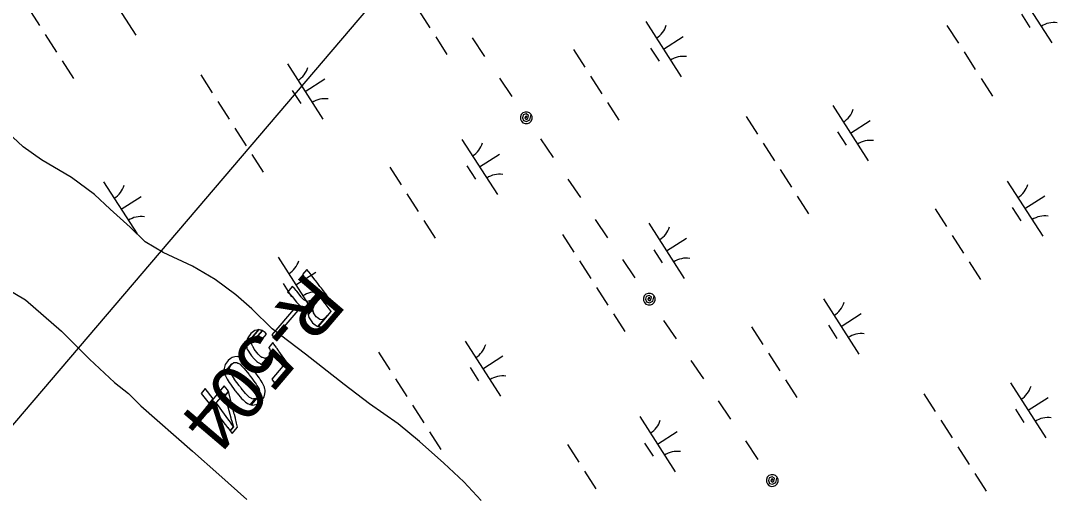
# Model space of a CAD drawing. Extents: x 3962991 to 3983549, y 181631 to 204078.
# Drawn here: x 3970895 to 3971685, y 196865 to 197226 of the extents above; entities that cross this region are included whole.
import ezdxf

# ---------------------------------------------------------------- set-up
doc = ezdxf.new("R2010")
doc.units = 0
for name, color, linetype in [('V-ANNO-MASK', 7, 'Continuous'), ('V-ANNO-MASK2', 7, 'Continuous'), ('V-RIVR-EDGE', 7, 'Continuous'), ('V-RIVR-RANG-IDEN', 7, 'Continuous'), ('V-UTIL-LINE', 7, 'Continuous'), ('V-WETL-SWMP', 7, 'Continuous')]:
    doc.layers.add(name, color=color, linetype=linetype)

msp = doc.modelspace()

# ---------------------------------------------------------------- linework, layer by layer
at = {"layer": 'V-ANNO-MASK2'}
for points in [[(3971114.6, 197035.12), (3971113.38, 197036.71), (3971110.05, 197032.8), (3971111.27, 197031.21), (3971111.53, 197030.87), (3971112.78, 197029.26), (3971113.16, 197028.76), (3971116.45, 197024.49), (3971116.87, 197023.95), (3971118.41, 197021.95), (3971119.05, 197021.13), (3971120.06, 197019.82), (3971120.78, 197018.87), (3971121.01, 197018.57), (3971121.21, 197018.32), (3971112.09, 197007.59), (3971113.72, 197007.73), (3971116.3, 197009.24), (3971115.18, 197007.38), (3971114.16, 197004.26), (3971114.22, 197003.89), (3971123.72, 197015.06), (3971123.84, 197014.91), (3971124.49, 197014.06), (3971125.57, 197012.67), (3971125.91, 197012.22), (3971128.06, 197009.43), (3971128.63, 197008.7), (3971130.23, 197006.62), (3971131.4, 197005.11), (3971131.64, 197004.79), (3971131.65, 197004.79), (3971131.75, 197004.66), (3971131.79, 197004.6), (3971121.99, 196993.07), (3971125.62, 196992.94), (3971128.9, 196994.87), (3971131.91, 196998.14), (3971137.79, 197005.04), (3971137.68, 197005.19), (3971136.9, 197006.2), (3971135.12, 197008.51), (3971135.08, 197008.57), (3971134.97, 197008.7), (3971134.73, 197009.02), (3971133.56, 197010.54), (3971131.96, 197012.61), (3971131.39, 197013.35), (3971129.24, 197016.13), (3971128.9, 197016.58), (3971127.82, 197017.98), (3971127.17, 197018.83), (3971127.05, 197018.98), (3971126.87, 197019.21), (3971126.1, 197020.22), (3971125.88, 197020.51), (3971125.26, 197021.3), (3971124.54, 197022.24), (3971124.35, 197022.49), (3971124.12, 197022.79), (3971123.39, 197023.73), (3971122.37, 197025.04), (3971121.74, 197025.87), (3971120.2, 197027.87), (3971119.79, 197028.41), (3971116.49, 197032.68), (3971116.11, 197033.17), (3971114.86, 197034.79)], [(3971103.72, 197022.33), (3971102.32, 197023.71), (3971098.69, 197019.44), (3971100.22, 197018.21), (3971100.51, 197017.92), (3971101.92, 197016.48), (3971102.3, 197016), (3971105.66, 197011.8), (3971106.09, 197011.27), (3971107.83, 197009.52), (3971108.55, 197008.79), (3971110.05, 197008.05), (3971111.13, 197007.51), (3971111.65, 197007.56), (3971112.09, 197007.59), (3971118.06, 197014.62), (3971116.09, 197012.78), (3971115.51, 197012.66), (3971113.63, 197012.25), (3971112.11, 197012.98), (3971111.16, 197013.43), (3971109.47, 197015.24), (3971109.01, 197015.73), (3971105.71, 197020.01), (3971105.32, 197020.48), (3971104.01, 197022.03)], [(3971106.75, 197005.45), (3971104.79, 197008), (3971086.77, 196986.81), (3971088.73, 196984.26)], [(3971118.92, 197009.12), (3971120.99, 197011.85), (3971114.22, 197003.89), (3971114.26, 197003.65), (3971114.5, 197002.31), (3971117.94, 197006.36)], [(3971118.39, 197004.23), (3971117.94, 197006.36), (3971114.5, 197002.31), (3971114.88, 197000.1), (3971115.21, 196999.63), (3971117.27, 196996.74), (3971117.81, 196995.98), (3971119.87, 196994.44), (3971121.38, 196993.32), (3971121.69, 196993.08), (3971121.9, 196993.08), (3971127.39, 196999.53), (3971126.84, 196999.15), (3971125.55, 196998.23), (3971123.23, 196998.39), (3971121.26, 197000.03), (3971120.56, 197000.61), (3971118.54, 197003.55)], [(3971129.1, 197001.43), (3971127.38, 196999.53), (3971121.9, 196993.08), (3971121.99, 196993.07)], [(3971071.83, 196988.48), (3971070.87, 196987.71), (3971068.47, 196984.52), (3971068.01, 196983.23), (3971067.12, 196980.68), (3971067.29, 196979.47), (3971076.91, 196990.78), (3971075.39, 196990.41), (3971073.79, 196990.03)], [(3971078.18, 196990.41), (3971076.9, 196990.77), (3971067.29, 196979.47), (3971067.51, 196977.86), (3971073.07, 196984.4), (3971074.75, 196985.66), (3971075.07, 196985.9), (3971076.05, 196985.9), (3971076.05, 196985.91), (3971076.17, 196985.91), (3971079.64, 196989.99), (3971079.54, 196990.01), (3971078.76, 196990.24), (3971078.67, 196990.27)], [(3971080.09, 196989.65), (3971079.63, 196989.98), (3971076.17, 196985.91), (3971076.91, 196985.91), (3971077.08, 196985.82), (3971078.48, 196984.99), (3971078.54, 196984.94), (3971079.67, 196983.84), (3971082.68, 196987.38), (3971081.61, 196988.55), (3971081.56, 196988.6), (3971080.25, 196989.54)], [(3971071.69, 196982.06), (3971073.07, 196984.4), (3971067.51, 196977.87), (3971067.59, 196977.24), (3971067.61, 196977.13), (3971067.74, 196976.14), (3971067.8, 196976.06), (3971068.11, 196975.56), (3971068.22, 196975.4), (3971069.12, 196973.98), (3971069.17, 196973.91), (3971070.21, 196972.27), (3971071.16, 196970.78), (3971073.28, 196968.48), (3971075.23, 196966.37), (3971075.37, 196966.22), (3971075.91, 196965.93), (3971076.35, 196965.69), (3971077.79, 196964.89), (3971078.09, 196964.72), (3971078.84, 196964.3), (3971078.84, 196964.31), (3971079.01, 196964.21), (3971083.64, 196969.65), (3971083.25, 196969.49), (3971081.55, 196968.79), (3971081.2, 196968.91), (3971079.55, 196969.45), (3971079.04, 196969.61), (3971078.6, 196970.02), (3971078.45, 196970.15), (3971076.34, 196972.08), (3971074.41, 196974.6), (3971073.35, 196975.96), (3971072.43, 196977.75), (3971072.39, 196977.82), (3971071.6, 196979.37), (3971071.61, 196979.67), (3971071.64, 196980.59), (3971071.65, 196980.73), (3971071.69, 196981.92)], [(3971087.68, 196980.69), (3971087.55, 196980.86), (3971084.42, 196977.18), (3971084.54, 196977), (3971084.86, 196976.45), (3971085.13, 196976), (3971085.55, 196974.02), (3971085.42, 196973.34), (3971085.43, 196973.35), (3971085.09, 196971.66), (3971083.63, 196969.65), (3971079.01, 196964.21), (3971079.31, 196964.04), (3971080.44, 196964.11), (3971087.88, 196972.85), (3971088.68, 196971.74), (3971088.99, 196971.31), (3971089.23, 196970.98), (3971095.06, 196962.87), (3971086.66, 196952.99), (3971089.15, 196949.77), (3971100.39, 196962.99), (3971098, 196966.33), (3971092.17, 196974.44), (3971091.93, 196974.76), (3971091.62, 196975.2), (3971090.82, 196976.31), (3971090.33, 196977), (3971090.13, 196977.28), (3971090.01, 196977.44), (3971089.51, 196978.15), (3971089.3, 196978.43), (3971088.33, 196979.77), (3971088.04, 196980.19)], [(3971087.85, 196970.76), (3971087.88, 196972.85), (3971080.44, 196964.11), (3971082.29, 196964.22), (3971083, 196964.26), (3971084.35, 196965.24), (3971085.6, 196966.16), (3971085.6, 196966.16), (3971087.26, 196968.67), (3971087.52, 196969.58)], [(3971054.94, 196968.38), (3971053.53, 196967.27), (3971051.28, 196964.08), (3971051.04, 196963.17), (3971050.24, 196960.22), (3971050.52, 196958.82), (3971050.68, 196957.98), (3971056.32, 196964.61), (3971056.57, 196964.77), (3971057.92, 196965.62), (3971058.53, 196965.65), (3971059.03, 196965.68), (3971060, 196965.73), (3971060.98, 196965.19), (3971060.99, 196965.19), (3971062.56, 196964.32), (3971063.49, 196963.37), (3971064.45, 196962.39), (3971065.47, 196961.35), (3971065.57, 196961.24), (3971069.12, 196956.79), (3971069.55, 196956.27), (3971070.35, 196955.25), (3971070.72, 196954.75), (3971070.72, 196954.76), (3971073.87, 196950.44), (3971073.88, 196950.45), (3971074.13, 196950.1), (3971074.87, 196949.09), (3971075.44, 196948.08), (3971076.27, 196946.62), (3971076.99, 196945.33), (3971077.02, 196945.21), (3971077.3, 196943.84), (3971077.42, 196943.24), (3971077.55, 196942.63), (3971077.27, 196941.61), (3971077.28, 196941.61), (3971077, 196940.59), (3971075.77, 196938.99), (3971071.07, 196933.47), (3971071.85, 196933.2), (3971073.29, 196933.49), (3971075.48, 196933.93), (3971076.95, 196935.07), (3971080.85, 196939.66), (3971081.05, 196940.48), (3971081.78, 196943.47), (3971081.56, 196944.61), (3971081.37, 196945.58), (3971081.34, 196945.7), (3971081.24, 196946.27), (3971081.12, 196946.84), (3971081, 196947.45), (3971080.76, 196947.91), (3971080.2, 196948.96), (3971080.15, 196949.06), (3971079.45, 196950.37), (3971078.66, 196951.86), (3971078, 196952.77), (3971077.26, 196953.79), (3971077.01, 196954.14), (3971073.88, 196958.47), (3971073.5, 196958.95), (3971072.68, 196959.96), (3971072.25, 196960.48), (3971068.67, 196964.89), (3971068.57, 196965), (3971067.51, 196965.98), (3971066.5, 196966.91), (3971065.52, 196967.8), (3971064.22, 196968.99), (3971064.21, 196968.99), (3971063.1, 196969.38), (3971062.39, 196969.63), (3971062.02, 196969.76), (3971061.57, 196969.91), (3971061.09, 196970.09), (3971061, 196970.11), (3971060.33, 196970.35), (3971058.58, 196970.03), (3971056.54, 196969.64)], [(3971055.09, 196963.02), (3971056.32, 196964.61), (3971050.68, 196957.98), (3971050.71, 196957.87)], [(3971054.8, 196961.95), (3971055.08, 196963.02), (3971050.71, 196957.87), (3971050.82, 196957.27), (3971050.93, 196956.72), (3971051.02, 196956.26), (3971051.38, 196955.6), (3971051.94, 196954.56), (3971051.95, 196954.55), (3971052.84, 196952.89), (3971053.52, 196951.64), (3971054.34, 196950.49), (3971055.2, 196949.27), (3971055.2, 196949.28), (3971055.29, 196949.15), (3971058.62, 196944.45), (3971059.05, 196943.93), (3971059.88, 196942.93), (3971060.27, 196942.46), (3971063.62, 196938.39), (3971063.89, 196938.07), (3971064.81, 196937.27), (3971065.64, 196936.55), (3971066.82, 196935.51), (3971067.87, 196934.61), (3971067.94, 196934.54), (3971069.07, 196934.15), (3971069.07, 196934.16), (3971069.55, 196933.99), (3971070.05, 196933.82), (3971070.51, 196933.66), (3971074.19, 196937.98), (3971073.56, 196937.95), (3971072.89, 196937.91), (3971072.23, 196937.87), (3971071.22, 196938.39), (3971071.13, 196938.44), (3971069.86, 196939.08), (3971068.72, 196940.17), (3971067.93, 196940.93), (3971067.05, 196941.78), (3971066.74, 196942.06), (3971063.41, 196946.16), (3971063.02, 196946.64), (3971062.21, 196947.64), (3971061.81, 196948.19), (3971058.44, 196952.85), (3971058.34, 196952.97), (3971057.47, 196954.18), (3971056.74, 196955.44), (3971056.04, 196956.65), (3971055.1, 196958.27), (3971055.09, 196958.27), (3971054.82, 196959.64), (3971054.64, 196960.52), (3971054.55, 196960.97)], [(3971042.12, 196937.97), (3971036.08, 196945.82), (3971032.99, 196942.19), (3971039.03, 196934.34)], [(3971052.89, 196944.91), (3971050.57, 196947.91), (3971035.93, 196930.69), (3971038.25, 196927.7), (3971050.45, 196942.04), (3971050.92, 196940.32), (3971053.81, 196943.72)], [(3971058.13, 196926.53), (3971053.81, 196943.72), (3971050.92, 196940.32), (3971055.48, 196923.42), (3971055.6, 196922.98), (3971056.43, 196920.17), (3971056.48, 196920.03), (3971057.57, 196916.68), (3971055, 196913.65), (3971056.62, 196911.54), (3971060.69, 196916.32), (3971059.91, 196919.43), (3971059.01, 196923.01), (3971058.98, 196923.16), (3971058.24, 196926.08)], [(3971045.32, 196933.74), (3971044.43, 196934.96), (3971041.35, 196931.35), (3971042.28, 196930.16), (3971051.28, 196918.48), (3971051.52, 196918.17), (3971053.05, 196916.19), (3971053.12, 196916.09), (3971055, 196913.65), (3971057.57, 196916.68), (3971055.85, 196919.3), (3971055.78, 196919.41), (3971054.33, 196921.48), (3971054.1, 196921.79)], [(3971075.48, 196938.81), (3971074.18, 196937.98), (3971070.51, 196933.66), (3971070.97, 196933.5), (3971071.07, 196933.47), (3971075.77, 196938.99)], [(3971078.52, 196936.3), (3971080.85, 196939.66), (3971076.95, 196935.07), (3971078.51, 196936.29)]]:
    msp.add_lwpolyline(points, close=True, dxfattribs=at)
at = {"layer": 'V-RIVR-EDGE'}
msp.add_lwpolyline([(3970873.05, 197028.8), (3970899.17, 197013.36), (3970926.48, 196989.62), (3970947.85, 196968.25), (3970966.84, 196950.44), (3970977.53, 196942.13), (3970987.02, 196932.63), (3971026.2, 196898.2), (3971046.38, 196880.39), (3971067.75, 196861.4)], dxfattribs=at)
at = {"layer": 'V-UTIL-LINE'}
msp.add_line((3970065.58, 195951.74), (3971473.5, 197603.23), dxfattribs=at)
for points in [[(3971239.36, 197213.04), (3971248.9, 197198.97)], [(3971260.12, 197182.42), (3971269.66, 197168.35)], [(3971280.61, 197152.19), (3971281.13, 197153.53), (3971280, 197153.25), (3971279.53, 197151.96), (3971280.48, 197150.85), (3971281.93, 197151.73), (3971282.43, 197154.03), (3971280.61, 197155.13), (3971278.3, 197154.35), (3971277.76, 197152.13), (3971278.58, 197150.05), (3971280.9, 197149.37), (3971283.26, 197150.78), (3971284.33, 197154.72), (3971283.08, 197155.95), (3971281.45, 197156.61), (3971279.7, 197156.6), (3971278.08, 197155.92), (3971276.85, 197154.67), (3971276.19, 197153.04), (3971276.2, 197151.28), (3971276.88, 197149.67), (3971278.13, 197148.43), (3971279.76, 197147.77), (3971281.51, 197147.78), (3971283.13, 197148.47), (3971284.36, 197149.72), (3971285.02, 197151.34), (3971285.01, 197153.1), (3971284.33, 197154.72)], [(3971291.55, 197136.07), (3971301.08, 197121.99)], [(3971312.31, 197105.44), (3971321.85, 197091.37)], [(3971333.07, 197074.82), (3971342.61, 197060.74)], [(3971353.83, 197044.19), (3971363.37, 197030.12)], [(3971374.32, 197013.96), (3971374.84, 197015.3), (3971373.71, 197015.03), (3971373.24, 197013.74), (3971374.2, 197012.62), (3971375.65, 197013.51), (3971376.14, 197015.8), (3971374.32, 197016.9), (3971372.02, 197016.12), (3971371.47, 197013.9), (3971372.3, 197011.82), (3971374.61, 197011.15), (3971376.98, 197012.55), (3971378.04, 197016.49), (3971376.79, 197017.72), (3971375.17, 197018.38), (3971373.41, 197018.37), (3971371.79, 197017.69), (3971370.56, 197016.44), (3971369.9, 197014.81), (3971369.91, 197013.06), (3971370.59, 197011.44), (3971371.84, 197010.21), (3971373.47, 197009.54), (3971375.23, 197009.56), (3971376.84, 197010.24), (3971378.08, 197011.49), (3971378.74, 197013.12), (3971378.73, 197014.87), (3971378.04, 197016.49)], [(3971385.26, 196997.84), (3971394.8, 196983.77)], [(3971406.02, 196967.21), (3971415.56, 196953.14)], [(3971426.78, 196936.59), (3971436.32, 196922.52)], [(3971447.54, 196905.96), (3971457.08, 196891.89)], [(3971468.03, 196875.74), (3971468.55, 196877.08), (3971467.42, 196876.8), (3971466.96, 196875.51), (3971467.91, 196874.39), (3971469.36, 196875.28), (3971469.86, 196877.57), (3971468.03, 196878.68), (3971465.73, 196877.9), (3971465.19, 196875.67), (3971466.01, 196873.59), (3971468.32, 196872.92), (3971470.69, 196874.33), (3971471.76, 196878.26), (3971470.51, 196879.49), (3971468.88, 196880.16), (3971467.12, 196880.14), (3971465.51, 196879.46), (3971464.27, 196878.21), (3971463.61, 196876.58), (3971463.62, 196874.83), (3971464.31, 196873.21), (3971465.56, 196871.98), (3971467.18, 196871.32), (3971468.94, 196871.33), (3971470.56, 196872.01), (3971471.79, 196873.26), (3971472.45, 196874.89), (3971472.44, 196876.64), (3971471.76, 196878.26)]]:
    msp.add_lwpolyline(points, dxfattribs=at)
at = {"layer": 'V-WETL-SWMP'}
for p, q in [((3970956.13, 197257.26), (3970983.11, 197215.16)), ((3971654.11, 197251.36), (3971681.1, 197209.27)), ((3970901.22, 197235.96), (3970909.86, 197222.49)), ((3971198.63, 197234.19), (3971207.27, 197220.72)), ((3971371.63, 197225.54), (3971398.62, 197183.44)), ((3971657.87, 197231.2), (3971664.35, 197221.1)), ((3971601.18, 197222.68), (3971609.82, 197209.21)), ((3970914.17, 197215.75), (3970922.81, 197202.28)), ((3971211.59, 197213.99), (3971220.22, 197200.52)), ((3971385.12, 197204.49), (3971400.28, 197214.2)), ((3971316.73, 197204.24), (3971325.36, 197190.77)), ((3971375.39, 197205.38), (3971381.87, 197195.27)), ((3971614.14, 197202.47), (3971622.77, 197189.01)), ((3970927.13, 197195.55), (3970935.76, 197182.08)), ((3971098.58, 197193.3), (3971125.56, 197151.21)), ((3971032.7, 197184.83), (3971041.33, 197171.36)), ((3971112.07, 197172.26), (3971127.22, 197181.97)), ((3971329.68, 197184.03), (3971338.31, 197170.56)), ((3971627.09, 197182.27), (3971635.73, 197168.8)), ((3971102.33, 197173.14), (3971108.81, 197163.04)), ((3970897.39, 197130.08), (3970859.96, 197164.87)), ((3971045.65, 197164.63), (3971054.28, 197151.16)), ((3971342.63, 197163.83), (3971351.27, 197150.36)), ((3971514.08, 197161.58), (3971541.07, 197119.49)), ((3971448.2, 197153.11), (3971456.84, 197139.64)), ((3971527.57, 197140.54), (3971542.73, 197150.25)), ((3971058.6, 197144.42), (3971067.24, 197130.95)), ((3971517.84, 197141.43), (3971524.32, 197131.32)), ((3971231.6, 197135.76), (3971258.59, 197093.67)), ((3971461.15, 197132.91), (3971469.79, 197119.44)), ((3970911.24, 197120.09), (3970897.39, 197130.08)), ((3971071.55, 197124.22), (3971080.19, 197110.75)), ((3971245.09, 197114.72), (3971260.25, 197124.43)), ((3970934.09, 197106.62), (3970911.24, 197120.09)), ((3971235.36, 197115.6), (3971241.84, 197105.5)), ((3971176.69, 197114.47), (3971185.33, 197101)), ((3971474.11, 197112.7), (3971482.74, 197099.23)), ((3970951.56, 197093.68), (3970934.09, 197106.62)), ((3970958.54, 197103.53), (3970984.11, 197063.65)), ((3971647.11, 197104.04), (3971674.09, 197061.95)), ((3970963.63, 197082.48), (3970951.56, 197093.68)), ((3970972.04, 197082.48), (3970987.19, 197092.2)), ((3971189.65, 197094.26), (3971198.28, 197080.79)), ((3971487.06, 197092.5), (3971495.69, 197079.03)), ((3971660.6, 197083), (3971675.75, 197092.71)), ((3971650.86, 197083.88), (3971657.34, 197073.78)), ((3970978.72, 197068.92), (3970963.63, 197082.48)), ((3971592.2, 197082.75), (3971600.84, 197069.28)), ((3970990.2, 197057.7), (3970978.72, 197068.92)), ((3971202.6, 197074.06), (3971211.24, 197060.59)), ((3971374.05, 197071.81), (3971401.03, 197029.72)), ((3971308.17, 197063.34), (3971316.8, 197049.87)), ((3971387.54, 197050.76), (3971402.7, 197060.48)), ((3971605.15, 197062.54), (3971613.79, 197049.07)), ((3971004.03, 197049.5), (3970990.2, 197057.7)), ((3971377.81, 197051.65), (3971384.28, 197041.55)), ((3971026.25, 197039.01), (3971004.03, 197049.5)), ((3971091.57, 197045.99), (3971118.55, 197003.9)), ((3971043.68, 197029.07), (3971026.25, 197039.01)), ((3971321.12, 197043.13), (3971329.76, 197029.66)), ((3971618.11, 197042.34), (3971626.74, 197028.87)), ((3971059.34, 197017.3), (3971043.68, 197029.07)), ((3971105.06, 197024.94), (3971120.21, 197034.66)), ((3971095.33, 197025.83), (3971101.8, 197015.73)), ((3971334.07, 197022.93), (3971342.71, 197009.46)), ((3971071.41, 197006.7), (3971059.34, 197017.3)), ((3971507.07, 197014.27), (3971534.06, 196972.18)), ((3971087.12, 196991.35), (3971071.41, 197006.7)), ((3971347.03, 197002.72), (3971355.66, 196989.25)), ((3971520.57, 196993.22), (3971535.72, 197002.94)), ((3971112.42, 196971.94), (3971087.12, 196991.35)), ((3971452.17, 196992.97), (3971460.8, 196979.5)), ((3971510.83, 196994.11), (3971517.31, 196984.01)), ((3971234.02, 196982.04), (3971261, 196939.95)), ((3971168.14, 196973.56), (3971176.77, 196960.09)), ((3971465.12, 196972.77), (3971473.76, 196959.3)), ((3971141.95, 196948.99), (3971112.42, 196971.94)), ((3971247.51, 196960.99), (3971262.66, 196970.71)), ((3971237.78, 196961.88), (3971244.25, 196951.78)), ((3971161.23, 196934.29), (3971141.95, 196948.99)), ((3971181.09, 196953.36), (3971189.73, 196939.89)), ((3971478.07, 196952.56), (3971486.71, 196939.09)), ((3971649.52, 196950.32), (3971676.51, 196908.23)), ((3971583.64, 196941.84), (3971592.28, 196928.37)), ((3971182.91, 196919.02), (3971161.23, 196934.29)), ((3971194.04, 196933.15), (3971202.68, 196919.68)), ((3971663.02, 196929.27), (3971678.17, 196938.99)), ((3971653.28, 196930.16), (3971659.76, 196920.06)), ((3971199.19, 196905.47), (3971182.91, 196919.02)), ((3971367.04, 196924.5), (3971394.03, 196882.4)), ((3971596.59, 196921.64), (3971605.23, 196908.17)), ((3971207, 196912.95), (3971215.63, 196899.48)), ((3971380.53, 196903.45), (3971395.69, 196913.16)), ((3971217.9, 196888.97), (3971199.19, 196905.47)), ((3971312.14, 196903.2), (3971320.77, 196889.73)), ((3971370.8, 196904.34), (3971377.28, 196894.23)), ((3971609.55, 196901.44), (3971618.18, 196887.97)), ((3971232.99, 196874.81), (3971217.9, 196888.97)), ((3971325.09, 196882.99), (3971333.72, 196869.52)), ((3971622.5, 196881.23), (3971631.14, 196867.76)), ((3971246.29, 196860.63), (3971232.99, 196874.81))]:
    msp.add_line(p, q, dxfattribs=at)
for centre, start, end in [((3971370.42, 197227.87), 301.89187, 343.43553), ((3971682.71, 197207.19), 81.89186, 123.43552), ((3971400.23, 197181.36), 81.89186, 123.43552), ((3971097.36, 197195.64), 301.89187, 343.43553), ((3971127.18, 197149.13), 81.89186, 123.43552), ((3971512.87, 197163.92), 301.89187, 343.43553), ((3971230.39, 197138.1), 301.89187, 343.43553), ((3971542.68, 197117.41), 81.89186, 123.43552), ((3971260.2, 197091.59), 81.89186, 123.43552), ((3970957.33, 197105.87), 301.89187, 343.43553), ((3971645.89, 197106.38), 301.89187, 343.43553), ((3970987.14, 197059.36), 81.89186, 123.43552), ((3971675.71, 197059.87), 81.89186, 123.43552), ((3971372.83, 197074.15), 301.89187, 343.43553), ((3971402.65, 197027.64), 81.89186, 123.43552), ((3971090.35, 197048.32), 301.89187, 343.43553), ((3971120.17, 197001.82), 81.89186, 123.43552), ((3971505.86, 197016.6), 301.89187, 343.43553), ((3971535.67, 196970.1), 81.89186, 123.43552), ((3971232.8, 196984.37), 301.89187, 343.43553), ((3971262.62, 196937.87), 81.89186, 123.43552), ((3971648.31, 196952.65), 301.89187, 343.43553), ((3971365.83, 196926.83), 301.89187, 343.43553), ((3971678.12, 196906.15), 81.89186, 123.43552), ((3971395.64, 196880.32), 81.89186, 123.43552)]:
    msp.add_arc(centre, 17.62, start, end, dxfattribs=at)

# ---------------------------------------------------------------- texts
at = {"layer": 'V-ANNO-MASK'}
msp.add_text('R-504  ', height=41.5, rotation=229.62238, dxfattribs=at).set_placement((3971112.97, 197036.23))
at = {"layer": 'V-RIVR-RANG-IDEN'}
msp.add_text('R-504  ', height=41.5, rotation=229.62238, dxfattribs=at).set_placement((3971112.97, 197036.23))

doc.saveas('drawing.dxf')
